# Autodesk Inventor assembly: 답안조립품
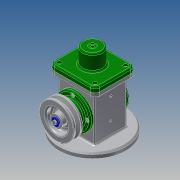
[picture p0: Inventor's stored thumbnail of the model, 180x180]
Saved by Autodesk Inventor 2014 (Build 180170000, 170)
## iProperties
Created: 2019-08
Part Number: 답안조립품
Document SubType Name: Assembly
Designer: kb542-14
Author: kb542-14
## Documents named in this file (18)
- C:\Users\kb542-14\Desktop\490804V1040\답안조립품.iam
- C:\Users\kb542-14\Desktop\490804V1040\본체.ipt
- C:\Users\kb542-14\Desktop\490804V1040\E-링.ipt
- C:\Users\kb542-14\Desktop\490804V1040\V-벨트풀리.ipt
- C:\Users\kb542-14\Desktop\490804V1040\덮개.ipt
- C:\Users\kb542-14\Desktop\490804V1040\뒤커버.ipt
- C:\Users\kb542-14\Desktop\490804V1040\링크.ipt
- C:\Users\kb542-14\Desktop\490804V1040\베어링 17 x 40 x 12.ipt
- C:\Users\kb542-14\Desktop\490804V1040\볼트 M4 x 8.ipt
- C:\Users\kb542-14\Desktop\490804V1040\볼트 M4 x 10.ipt
- C:\Users\kb542-14\Desktop\490804V1040\슬라이더.ipt
- C:\Users\kb542-14\Desktop\490804V1040\앞커버.ipt
- C:\Users\kb542-14\Desktop\490804V1040\오일 실 17 30 8.ipt
- C:\Users\kb542-14\Desktop\490804V1040\와셔 4x16.ipt
- C:\Users\kb542-14\Desktop\490804V1040\클레비스 핀 6 x 22.ipt
- 클레비스 핀 6 x 22.ipt
- C:\Users\kb542-14\Desktop\490804V1040\키 4 x 4 x 12.ipt
- C:\Users\kb542-14\Desktop\490804V1040\편심축.ipt
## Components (2 placed, 2 different names)
1. E-링:1
2. V-벨트풀리:1
